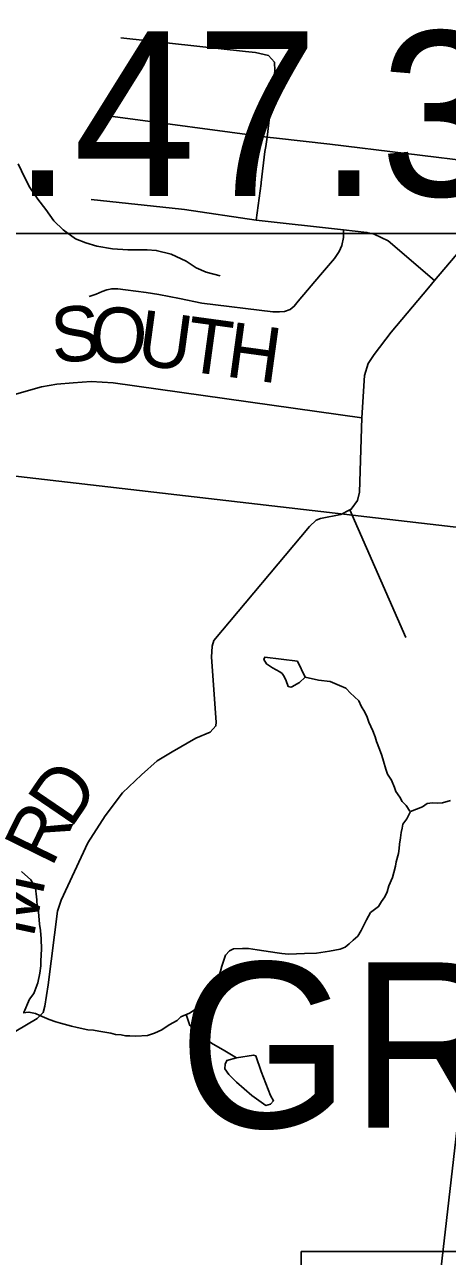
# Model space of a CAD drawing. Extents: x 0 to 34, y 0 to 22.
# Drawn here: x 4.331 to 4.767, y 17.836 to 19.105 of the extents above; entities that cross this region are included whole.
import ezdxf

# ---------------------------------------------------------------- set-up
doc = ezdxf.new("R2010")
doc.units = 0
for name, color, linetype in [('GM_X_Corporation', 7, 'Continuous'), ('GM_X_County_Road', 7, 'Continuous'), ('GM_X_County_Road_Text', 7, 'Continuous'), ('GM_X_Minor_Lake', 7, 'Continuous'), ('GM_X_Minor_River', 7, 'Continuous'), ('GM_X_Township_Road', 7, 'Continuous'), ('GM_X_Township_Text', 7, 'Continuous'), ('SH_Masking', 7, 'Continuous'), ('SH_Text', 7, 'Continuous')]:
    doc.layers.add(name, color=color, linetype=linetype)

msp = doc.modelspace()

# ---------------------------------------------------------------- linework, layer by layer
at = {"layer": 'GM_X_Corporation'}
for points in [[(3.9403, 19.7031), (4.9462, 19.5973), (4.8473, 18.5791), (3.8378, 18.696)], [(4.8473, 18.5791), (4.7377, 17.6243), (3.7435, 17.7155), (3.8378, 18.696)], [(4.8473, 18.5791), (5.8893, 18.4792), (5.7989, 17.4561), (4.7377, 17.6243)]]:
    msp.add_lwpolyline(points, close=True, dxfattribs=at)
at = {"layer": 'GM_X_County_Road'}
for points in [[(4.7476, 18.8343), (4.7539, 18.8418), (4.8412, 18.9443)], [(4.6787, 18.7002), (4.6817, 18.7438), (4.6855, 18.7562), (4.6915, 18.7656), (4.7091, 18.7883), (4.7476, 18.8343)], [(4.3134, 18.7223), (4.3485, 18.7321), (4.3642, 18.7347), (4.3813, 18.7361), (4.3999, 18.7376), (4.4223, 18.7362), (4.6787, 18.7002)], [(4.322, 18.0679), (4.344, 18.0812), (4.3503, 18.0871), (4.352, 18.0939), (4.3554, 18.1158), (4.3651, 18.1918), (4.3689, 18.2031), (4.3962, 18.2622), (4.4141, 18.2898), (4.432, 18.3135), (4.4516, 18.3323), (4.4679, 18.3466), (4.4834, 18.3559), (4.5078, 18.37), (4.5224, 18.3763), (4.5283, 18.3826), (4.5288, 18.3864), (4.5238, 18.4534), (4.5245, 18.4648), (4.5262, 18.4708), (4.6248, 18.5881), (4.6319, 18.5947), (4.6361, 18.5964), (4.6571, 18.6007), (4.6664, 18.6053), (4.6679, 18.606), (4.6742, 18.615), (4.6764, 18.6236), (4.6787, 18.7002)]]:
    msp.add_lwpolyline(points, dxfattribs=at)
at = {"layer": 'GM_X_Minor_Lake'}
for points in [[(4.6204, 18.4329), (4.6125, 18.4494), (4.5788, 18.4534), (4.5779, 18.4511), (4.5805, 18.4465), (4.5868, 18.4425), (4.5906, 18.4405), (4.5943, 18.4385), (4.5966, 18.4366), (4.5988, 18.4335), (4.6009, 18.4292), (4.603, 18.4231), (4.6057, 18.4226), (4.6065, 18.423)], [(4.6065, 18.423), (4.6146, 18.4273), (4.6204, 18.4329)], [(4.5653, 18.0018), (4.5798, 17.9915), (4.5848, 17.9929), (4.5879, 17.9963), (4.5847, 18.0017), (4.575, 18.0263), (4.5694, 18.0424), (4.5671, 18.0432), (4.5495, 18.0405)], [(4.5495, 18.0405), (4.5395, 18.0377), (4.538, 18.0339), (4.5375, 18.029), (4.5416, 18.0232), (4.5496, 18.0153)], [(4.5496, 18.0153), (4.5653, 18.0018)]]:
    msp.add_lwpolyline(points, dxfattribs=at)
at = {"layer": 'GM_X_Minor_River'}
for points in [[(4.3244, 18.962), (4.3315, 18.9474), (4.3366, 18.9377), (4.3446, 18.9257), (4.353, 18.9148), (4.3614, 18.9032), (4.371, 18.8938), (4.3836, 18.8847), (4.3942, 18.8806), (4.4055, 18.8772), (4.4217, 18.8745), (4.4376, 18.8733), (4.4574, 18.8735), (4.4669, 18.8728), (4.4823, 18.869), (4.4977, 18.8617), (4.5081, 18.8549), (4.5182, 18.8504), (4.5326, 18.8466)], [(4.6622, 18.4215), (4.6559, 18.4244), (4.6461, 18.4284), (4.634, 18.4299), (4.6204, 18.4329)], [(4.7284, 18.2949), (4.7244, 18.3007), (4.7204, 18.3046), (4.7179, 18.3093), (4.7139, 18.3151), (4.7125, 18.3193), (4.7093, 18.3267), (4.7054, 18.3329), (4.7037, 18.3379), (4.7013, 18.3463), (4.6996, 18.3521), (4.6972, 18.3587), (4.694, 18.3667), (4.6927, 18.3713), (4.6902, 18.3775), (4.686, 18.3864), (4.6843, 18.3918), (4.6818, 18.3968), (4.6782, 18.403), (4.6757, 18.4084), (4.6669, 18.4167), (4.6629, 18.421), (4.6622, 18.4215)], [(4.6033, 18.1475), (4.6197, 18.1481), (4.6322, 18.1484), (4.6456, 18.1506), (4.6566, 18.1525), (4.6616, 18.1546), (4.6659, 18.1579), (4.6699, 18.1619), (4.6746, 18.166), (4.6782, 18.1719), (4.6806, 18.1764), (4.6835, 18.1828), (4.6879, 18.1902), (4.6961, 18.1964), (4.699, 18.2016), (4.7025, 18.2064), (4.705, 18.2117), (4.7067, 18.2177), (4.7104, 18.2263), (4.7118, 18.2316), (4.7135, 18.238), (4.7144, 18.2425), (4.7166, 18.2512), (4.7172, 18.2561), (4.7177, 18.2606), (4.7187, 18.2674), (4.7193, 18.2727), (4.7205, 18.2773), (4.7211, 18.2814), (4.7254, 18.287), (4.7291, 18.2944), (4.7414, 18.2993), (4.7461, 18.3026), (4.7518, 18.3032), (4.7571, 18.303), (4.7621, 18.3032), (4.7701, 18.3056)], [(4.3302, 18.0871), (4.3363, 18.1009), (4.3407, 18.1068), (4.3449, 18.1177), (4.3467, 18.1279), (4.3478, 18.1354), (4.3479, 18.1404), (4.3487, 18.1525), (4.3483, 18.1632), (4.3475, 18.1716), (4.3466, 18.1781), (4.3455, 18.191), (4.3442, 18.1964), (4.3437, 18.2032), (4.3431, 18.2097), (4.3425, 18.2151), (4.34, 18.2197), (4.3375, 18.224), (4.328, 18.2327)], [(4.3298, 18.087), (4.3355, 18.0876), (4.3423, 18.0862), (4.3468, 18.0842), (4.3565, 18.08), (4.3632, 18.0775), (4.3681, 18.0762), (4.3794, 18.0731), (4.3854, 18.0718), (4.3964, 18.0695), (4.402, 18.0689), (4.4077, 18.068), (4.4202, 18.066), (4.4247, 18.0647), (4.4307, 18.0642), (4.4352, 18.0632), (4.4398, 18.0631), (4.4459, 18.0629), (4.4577, 18.0636), (4.465, 18.066), (4.4727, 18.0695), (4.4801, 18.0746), (4.4886, 18.0789), (4.4921, 18.0829), (4.5013, 18.0864), (4.508, 18.0911), (4.5116, 18.0967), (4.5194, 18.1037), (4.5227, 18.1104), (4.5282, 18.1155), (4.5298, 18.12), (4.5332, 18.1298), (4.5345, 18.1351), (4.5362, 18.1403), (4.5383, 18.1463), (4.5423, 18.1508), (4.5465, 18.1529), (4.5557, 18.1533), (4.5621, 18.1531), (4.5708, 18.1517), (4.5916, 18.1487), (4.5965, 18.1481), (4.6033, 18.1475)], [(4.4976, 18.085), (4.5015, 18.0738), (4.5122, 18.0636), (4.5237, 18.0557), (4.5376, 18.0477), (4.5495, 18.0405)]]:
    msp.add_lwpolyline(points, dxfattribs=at)
at = {"layer": 'GM_X_Township_Road'}
for p, q in [((4.57, 18.904), (4.575, 18.9418)), ((4.6664, 18.6053), (4.7242, 18.4739))]:
    msp.add_line(p, q, dxfattribs=at)
for points in [[(4.5797, 18.9797), (4.5811, 18.9895), (4.5891, 19.0577), (4.5888, 19.0666), (4.5827, 19.0736), (4.5693, 19.0766), (4.5589, 19.0777), (4.4303, 19.0917)], [(4.591, 18.9883), (4.5811, 18.9895), (4.4222, 19.0109)], [(4.8412, 18.9443), (4.8247, 18.9555), (4.8152, 18.9604), (4.8031, 18.9631), (4.6459, 18.9821), (4.591, 18.9883)], [(4.575, 18.9418), (4.5751, 18.9428), (4.5789, 18.9748), (4.5797, 18.9797)], [(4.4961, 18.915), (4.493, 18.9154), (4.3997, 18.9252)], [(4.7539, 18.8418), (4.7061, 18.8826), (4.6917, 18.8894), (4.684, 18.8913), (4.6599, 18.8939), (4.57, 18.904), (4.4961, 18.915)], [(4.3976, 18.8254), (4.405, 18.8278), (4.4112, 18.8305), (4.4159, 18.8322), (4.421, 18.8332), (4.4272, 18.8332), (4.4353, 18.8322), (4.4566, 18.8292), (4.4695, 18.8272), (4.491, 18.8231), (4.514, 18.8183), (4.5869, 18.8095), (4.5941, 18.8093), (4.5992, 18.8099), (4.605, 18.8117), (4.6091, 18.8152), (4.6133, 18.8205), (4.6363, 18.8476), (4.6505, 18.8643), (4.6555, 18.8717), (4.6581, 18.8779), (4.6599, 18.8862), (4.6599, 18.8939)]]:
    msp.add_lwpolyline(points, dxfattribs=at)
at = {"layer": 'SH_Masking'}
for points in [[(3.3595, 19.4095), (5.117, 19.4095), (5.117, 18.89), (3.3595, 18.89)], [(4.6164, 17.841), (6.3738, 17.841), (6.3738, 17.3215), (4.6164, 17.3215)]]:
    msp.add_lwpolyline(points, close=True, dxfattribs=at)
at = {"layer": 'SH_Text'}
for points in [[(3.3595, 19.4095), (5.117, 19.4095), (5.117, 18.89), (3.3595, 18.89)], [(4.6164, 17.841), (6.3738, 17.841), (6.3738, 17.3215), (4.6164, 17.3215)]]:
    msp.add_lwpolyline(points, close=True, dxfattribs=at)

# ---------------------------------------------------------------- texts
at = {"layer": 'GM_X_County_Road_Text'}
for s, rotation, p in [('S', 4.3899, (4.3604, 18.7566)), ('O', 355.1932, (4.3963, 18.7596)), ('U', 352.2832, (4.4453, 18.7555)), ('T', 352.2235, (4.4949, 18.7488)), ('H', 352.2207, (4.537, 18.743)), ('D', 55.779, (4.3786, 18.2757)), ('R', 63.8521, (4.3591, 18.2357)), ('M', 77.94, (4.3401, 18.1629))]:
    msp.add_text(s, height=0.0568, rotation=rotation, dxfattribs=at).set_placement(p)
at = {"layer": 'GM_X_Township_Text'}
msp.add_text('GREEN', height=0.17045, rotation=0, dxfattribs=at).set_placement((4.4896, 17.9684))
at = {"layer": 'SH_Text'}
msp.add_text('STA. 54.47.38', height=0.17, dxfattribs=at).set_placement((3.4967, 18.9287))

doc.saveas('drawing.dxf')
